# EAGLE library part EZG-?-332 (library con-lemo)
LEMO Connector Source: http://www.lemo.com/pdfs/catalog/ROW/German/unipole_multipole.pdf
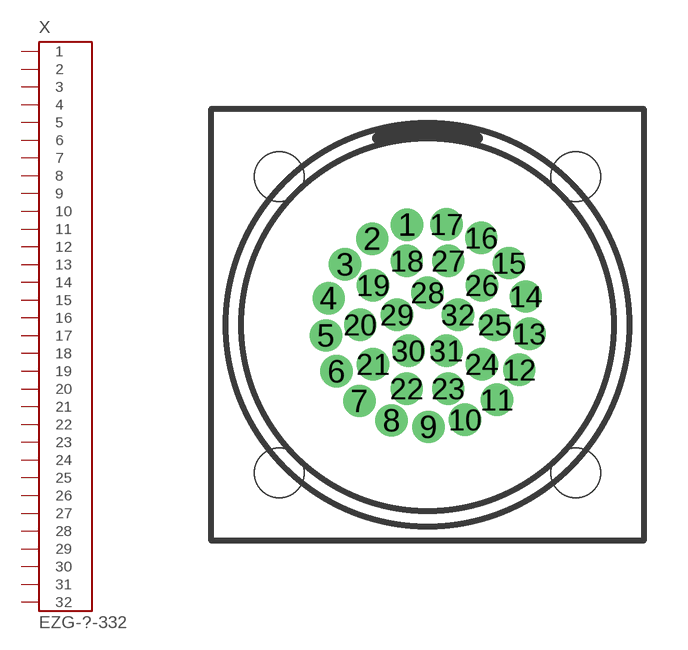
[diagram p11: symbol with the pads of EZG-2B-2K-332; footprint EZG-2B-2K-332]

Designator prefix X

## EZG-2B-332 (OC_FARNELL: unknown; OC_NEWARK: unknown)  [EZG-2B-2K-332]
1  1  pas
2  2  pas
3  3  pas
4  4  pas
5  5  pas
6  6  pas
7  7  pas
8  8  pas
9  9  pas
10  10  pas
11  11  pas
12  12  pas
13  13  pas
14  14  pas
15  15  pas
16  16  pas
17  17  pas
18  18  pas
19  19  pas
20  20  pas
21  21  pas
22  22  pas
23  23  pas
24  24  pas
25  25  pas
26  26  pas
27  27  pas
28  28  pas
29  29  pas
30  30  pas
31  31  pas
32  32  pas

## EZG-2K-332 (OC_FARNELL: unknown; OC_NEWARK: unknown)  [EZG-2B-2K-332]
Pads as for EZG-2B-2K-332

## Footprint EZG-2B-2K-332 (pad centres in mm)
LEMO Connector Source: http://www.lemo.com/pdfs/catalog/ROW/German/unipole_multipole.pdf
drill 0.6 pad 1 round: 1 -0.704,3.429; 2 -1.891,2.945; 3 -2.825,2.066; 4 -3.38,0.91; 5 -3.481,-0.368; 6 -3.114,-1.597; 7 -2.33,-2.611; 8 -1.233,-3.276; 9 0.029,-3.5; 10 1.288,-3.254; 11 2.373,-2.572; 12 3.141,-1.545; 13 3.486,-0.31; 14 3.364,0.966; 15 2.79,2.113; 16 1.842,2.976; 17 0.646,3.44; 18 -0.711,2.187; 19 -1.861,1.352; 20 -2.3,0; 21 -1.861,-1.352; 22 -0.711,-2.187; 23 0.711,-2.187; 24 1.861,-1.352; 25 2.3,0; 26 1.861,1.352; 27 0.711,2.187; 28 0,1.1; 29 -1.046,0.34; 30 -0.647,-0.89; 31 0.647,-0.89; 32 1.046,0.34
hole 1.7 at -5.08,5.08
hole 1.7 at 5.08,5.08
hole 1.7 at 5.08,-5.08
hole 1.7 at -5.08,-5.08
